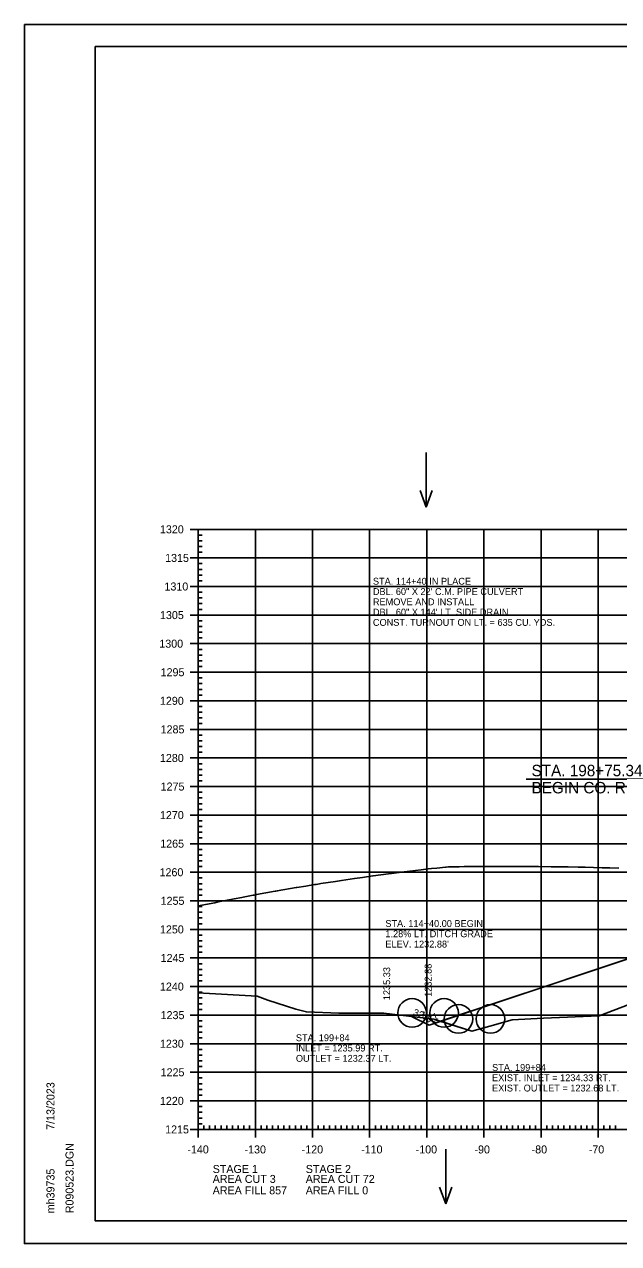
# Model space of a CAD drawing. Extents: x 1406028 to 1412453, y 321733 to 325986.
# Drawn here: x 1406419.5 to 1406523.5, y 323852.7 to 324066 of the extents above; entities that cross this region are included whole.
import ezdxf

# ---------------------------------------------------------------- set-up
doc = ezdxf.new("R2010")
doc.units = 0
for name, color, linetype in [('Default', 7, 'Continuous'), ('R_Axis', 7, 'Continuous'), ('R_Axis Annot', 7, 'Continuous'), ('R_Border', 7, 'Continuous'), ('R_Draft', 7, 'Continuous'), ('R_Drive', 7, 'Continuous'), ('R_Exist Surface', 7, 'Continuous'), ('R_Fin Surface', 7, 'Continuous'), ('R_Fin Surface Annot', 7, 'Continuous'), ('R_Grid', 7, 'Continuous'), ('R_Horz Alg Annot', 7, 'Continuous'), ('R_No Plot', 7, 'Continuous'), ('R_Water', 7, 'Continuous'), ('R_Water Annot', 7, 'Continuous')]:
    doc.layers.add(name, color=color, linetype=linetype)

msp = doc.modelspace()

# ---------------------------------------------------------------- linework, layer by layer
at = {"layer": 'R_Axis'}
for p, q in [((1406448.49, 323977.69), (1406451.29, 323977.69)), ((1406449.89, 323872.69), (1406449.89, 323977.69)), ((1406449.89, 323976.69), (1406450.59, 323976.69)), ((1406449.89, 323975.69), (1406450.59, 323975.69)), ((1406449.89, 323974.69), (1406450.59, 323974.69)), ((1406448.49, 323972.69), (1406451.29, 323972.69)), ((1406449.89, 323973.69), (1406450.59, 323973.69)), ((1406449.89, 323971.69), (1406450.59, 323971.69)), ((1406449.89, 323970.69), (1406450.59, 323970.69)), ((1406449.89, 323969.69), (1406450.59, 323969.69)), ((1406449.89, 323968.69), (1406450.59, 323968.69)), ((1406448.49, 323967.69), (1406451.29, 323967.69)), ((1406449.89, 323966.69), (1406450.59, 323966.69)), ((1406449.89, 323965.69), (1406450.59, 323965.69)), ((1406449.89, 323964.69), (1406450.59, 323964.69)), ((1406448.49, 323962.69), (1406451.29, 323962.69)), ((1406449.89, 323963.69), (1406450.59, 323963.69)), ((1406449.89, 323961.69), (1406450.59, 323961.69)), ((1406449.89, 323960.69), (1406450.59, 323960.69)), ((1406449.89, 323959.69), (1406450.59, 323959.69)), ((1406448.49, 323957.69), (1406451.29, 323957.69)), ((1406449.89, 323958.69), (1406450.59, 323958.69)), ((1406449.89, 323956.69), (1406450.59, 323956.69)), ((1406449.89, 323955.69), (1406450.59, 323955.69)), ((1406449.89, 323954.69), (1406450.59, 323954.69)), ((1406449.89, 323953.69), (1406450.59, 323953.69)), ((1406448.49, 323952.69), (1406451.29, 323952.69)), ((1406449.89, 323951.69), (1406450.59, 323951.69)), ((1406449.89, 323950.69), (1406450.59, 323950.69)), ((1406449.89, 323949.69), (1406450.59, 323949.69)), ((1406448.49, 323947.69), (1406451.29, 323947.69)), ((1406449.89, 323948.69), (1406450.59, 323948.69)), ((1406449.89, 323946.69), (1406450.59, 323946.69)), ((1406449.89, 323945.69), (1406450.59, 323945.69)), ((1406449.89, 323944.69), (1406450.59, 323944.69)), ((1406448.49, 323942.69), (1406451.29, 323942.69)), ((1406449.89, 323943.69), (1406450.59, 323943.69)), ((1406449.89, 323941.69), (1406450.59, 323941.69)), ((1406449.89, 323940.69), (1406450.59, 323940.69)), ((1406449.89, 323939.69), (1406450.59, 323939.69)), ((1406449.89, 323938.69), (1406450.59, 323938.69)), ((1406448.49, 323937.69), (1406451.29, 323937.69)), ((1406449.89, 323936.69), (1406450.59, 323936.69)), ((1406449.89, 323935.69), (1406450.59, 323935.69)), ((1406449.89, 323934.69), (1406450.59, 323934.69)), ((1406448.49, 323932.69), (1406451.29, 323932.69)), ((1406449.89, 323933.69), (1406450.59, 323933.69)), ((1406449.89, 323931.69), (1406450.59, 323931.69)), ((1406449.89, 323930.69), (1406450.59, 323930.69)), ((1406449.89, 323929.69), (1406450.59, 323929.69)), ((1406448.49, 323927.69), (1406451.29, 323927.69)), ((1406449.89, 323928.69), (1406450.59, 323928.69)), ((1406449.89, 323926.69), (1406450.59, 323926.69)), ((1406449.89, 323925.69), (1406450.59, 323925.69)), ((1406449.89, 323924.69), (1406450.59, 323924.69)), ((1406449.89, 323923.69), (1406450.59, 323923.69)), ((1406448.49, 323922.69), (1406451.29, 323922.69)), ((1406449.89, 323921.69), (1406450.59, 323921.69)), ((1406449.89, 323920.69), (1406450.59, 323920.69)), ((1406449.89, 323919.69), (1406450.59, 323919.69)), ((1406448.49, 323917.69), (1406451.29, 323917.69)), ((1406449.89, 323918.69), (1406450.59, 323918.69)), ((1406449.89, 323916.69), (1406450.59, 323916.69)), ((1406449.89, 323915.69), (1406450.59, 323915.69)), ((1406448.49, 323912.69), (1406451.29, 323912.69)), ((1406449.89, 323914.69), (1406450.59, 323914.69)), ((1406449.89, 323913.69), (1406450.59, 323913.69)), ((1406449.89, 323911.69), (1406450.59, 323911.69)), ((1406449.89, 323910.69), (1406450.59, 323910.69)), ((1406449.89, 323909.69), (1406450.59, 323909.69)), ((1406449.89, 323908.69), (1406450.59, 323908.69)), ((1406448.49, 323907.69), (1406451.29, 323907.69)), ((1406449.89, 323906.69), (1406450.59, 323906.69)), ((1406449.89, 323905.69), (1406450.59, 323905.69)), ((1406449.89, 323904.69), (1406450.59, 323904.69)), ((1406448.49, 323902.69), (1406451.29, 323902.69)), ((1406449.89, 323903.69), (1406450.59, 323903.69)), ((1406449.89, 323901.69), (1406450.59, 323901.69)), ((1406449.89, 323900.69), (1406450.59, 323900.69)), ((1406448.49, 323897.69), (1406451.29, 323897.69)), ((1406449.89, 323899.69), (1406450.59, 323899.69)), ((1406449.89, 323898.69), (1406450.59, 323898.69)), ((1406449.89, 323896.69), (1406450.59, 323896.69)), ((1406449.89, 323895.69), (1406450.59, 323895.69)), ((1406449.89, 323894.69), (1406450.59, 323894.69)), ((1406449.89, 323893.69), (1406450.59, 323893.69)), ((1406448.49, 323892.69), (1406451.29, 323892.69)), ((1406449.89, 323891.69), (1406450.59, 323891.69)), ((1406449.89, 323890.69), (1406450.59, 323890.69)), ((1406449.89, 323889.69), (1406450.59, 323889.69)), ((1406448.49, 323887.69), (1406451.29, 323887.69)), ((1406449.89, 323888.69), (1406450.59, 323888.69)), ((1406449.89, 323886.69), (1406450.59, 323886.69)), ((1406449.89, 323885.69), (1406450.59, 323885.69)), ((1406449.89, 323884.69), (1406450.59, 323884.69)), ((1406449.89, 323883.69), (1406450.59, 323883.69)), ((1406448.49, 323882.69), (1406451.29, 323882.69)), ((1406449.89, 323881.69), (1406450.59, 323881.69)), ((1406449.89, 323880.69), (1406450.59, 323880.69)), ((1406449.89, 323879.69), (1406450.59, 323879.69)), ((1406449.89, 323878.69), (1406450.59, 323878.69)), ((1406448.49, 323877.69), (1406451.29, 323877.69)), ((1406449.89, 323876.69), (1406450.59, 323876.69)), ((1406449.89, 323875.69), (1406450.59, 323875.69)), ((1406449.89, 323874.69), (1406450.59, 323874.69)), ((1406448.49, 323872.69), (1406451.29, 323872.69)), ((1406449.89, 323871.29), (1406449.89, 323874.09)), ((1406449.89, 323873.69), (1406450.59, 323873.69)), ((1406449.89, 323872.69), (1406729.89, 323872.69)), ((1406450.89, 323872.69), (1406450.89, 323873.39)), ((1406451.89, 323872.69), (1406451.89, 323873.39)), ((1406452.89, 323872.69), (1406452.89, 323873.39)), ((1406453.89, 323872.69), (1406453.89, 323873.39)), ((1406454.89, 323872.69), (1406454.89, 323873.39)), ((1406455.89, 323872.69), (1406455.89, 323873.39)), ((1406456.89, 323872.69), (1406456.89, 323873.39)), ((1406457.89, 323872.69), (1406457.89, 323873.39)), ((1406458.89, 323872.69), (1406458.89, 323873.39)), ((1406459.89, 323871.29), (1406459.89, 323874.09)), ((1406460.89, 323872.69), (1406460.89, 323873.39)), ((1406461.89, 323872.69), (1406461.89, 323873.39)), ((1406462.89, 323872.69), (1406462.89, 323873.39)), ((1406463.89, 323872.69), (1406463.89, 323873.39)), ((1406464.89, 323872.69), (1406464.89, 323873.39)), ((1406465.89, 323872.69), (1406465.89, 323873.39)), ((1406466.89, 323872.69), (1406466.89, 323873.39)), ((1406467.89, 323872.69), (1406467.89, 323873.39)), ((1406468.89, 323872.69), (1406468.89, 323873.39)), ((1406469.89, 323871.29), (1406469.89, 323874.09)), ((1406470.89, 323872.69), (1406470.89, 323873.39)), ((1406471.89, 323872.69), (1406471.89, 323873.39)), ((1406472.89, 323872.69), (1406472.89, 323873.39)), ((1406473.89, 323872.69), (1406473.89, 323873.39)), ((1406474.89, 323872.69), (1406474.89, 323873.39)), ((1406475.89, 323872.69), (1406475.89, 323873.39)), ((1406476.89, 323872.69), (1406476.89, 323873.39)), ((1406477.89, 323872.69), (1406477.89, 323873.39)), ((1406478.89, 323872.69), (1406478.89, 323873.39)), ((1406479.89, 323871.29), (1406479.89, 323874.09)), ((1406480.89, 323872.69), (1406480.89, 323873.39)), ((1406481.89, 323872.69), (1406481.89, 323873.39)), ((1406482.89, 323872.69), (1406482.89, 323873.39)), ((1406483.89, 323872.69), (1406483.89, 323873.39)), ((1406484.89, 323872.69), (1406484.89, 323873.39)), ((1406485.89, 323872.69), (1406485.89, 323873.39)), ((1406486.89, 323872.69), (1406486.89, 323873.39)), ((1406487.89, 323872.69), (1406487.89, 323873.39)), ((1406488.89, 323872.69), (1406488.89, 323873.39)), ((1406489.89, 323871.29), (1406489.89, 323874.09)), ((1406490.89, 323872.69), (1406490.89, 323873.39)), ((1406491.89, 323872.69), (1406491.89, 323873.39)), ((1406492.89, 323872.69), (1406492.89, 323873.39)), ((1406493.89, 323872.69), (1406493.89, 323873.39)), ((1406494.89, 323872.69), (1406494.89, 323873.39)), ((1406495.89, 323872.69), (1406495.89, 323873.39)), ((1406496.89, 323872.69), (1406496.89, 323873.39)), ((1406497.89, 323872.69), (1406497.89, 323873.39)), ((1406498.89, 323872.69), (1406498.89, 323873.39)), ((1406499.89, 323871.29), (1406499.89, 323874.09)), ((1406500.89, 323872.69), (1406500.89, 323873.39)), ((1406501.89, 323872.69), (1406501.89, 323873.39)), ((1406502.89, 323872.69), (1406502.89, 323873.39)), ((1406503.89, 323872.69), (1406503.89, 323873.39)), ((1406504.89, 323872.69), (1406504.89, 323873.39)), ((1406505.89, 323872.69), (1406505.89, 323873.39)), ((1406506.89, 323872.69), (1406506.89, 323873.39)), ((1406507.89, 323872.69), (1406507.89, 323873.39)), ((1406508.89, 323872.69), (1406508.89, 323873.39)), ((1406509.89, 323871.29), (1406509.89, 323874.09)), ((1406510.89, 323872.69), (1406510.89, 323873.39)), ((1406511.89, 323872.69), (1406511.89, 323873.39)), ((1406512.89, 323872.69), (1406512.89, 323873.39)), ((1406513.89, 323872.69), (1406513.89, 323873.39)), ((1406514.89, 323872.69), (1406514.89, 323873.39)), ((1406515.89, 323872.69), (1406515.89, 323873.39)), ((1406516.89, 323872.69), (1406516.89, 323873.39)), ((1406517.89, 323872.69), (1406517.89, 323873.39)), ((1406518.89, 323872.69), (1406518.89, 323873.39)), ((1406519.89, 323871.29), (1406519.89, 323874.09)), ((1406520.89, 323872.69), (1406520.89, 323873.39)), ((1406521.89, 323872.69), (1406521.89, 323873.39)), ((1406522.89, 323872.69), (1406522.89, 323873.39))]:
    msp.add_line(p, q, dxfattribs=at)
at = {"layer": 'R_Axis Annot'}
msp.add_line((1406507.3, 323933.99), (1406537.31, 323933.99), dxfattribs=at)
at = {"layer": 'R_Border'}
for p, q in [((1406431.89, 324062.15), (1406748.07, 324062.15)), ((1406431.89, 323856.69), (1406431.89, 324062.15)), ((1406431.89, 323856.69), (1406431.89, 323856.69)), ((1406748.07, 323856.69), (1406431.89, 323856.69))]:
    msp.add_line(p, q, dxfattribs=at)
at = {"layer": 'R_Exist Surface'}
msp.add_lwpolyline([(1406449.89, 323896.58), (1406450.83, 323896.53), (1406460.23, 323896.02), (1406462.1, 323895.33), (1406466.95, 323893.73), (1406468.82, 323893.25), (1406474.52, 323893.03), (1406482.35, 323893.02), (1406491.1, 323891.96), (1406491.18, 323891.96), (1406491.23, 323891.94), (1406497.79, 323889.9), (1406500.93, 323890.78), (1406504.83, 323891.87), (1406510.29, 323892.16), (1406520.03, 323892.56), (1406532.75, 323897.43)], dxfattribs=at)
at = {"layer": 'R_Fin Surface'}
for points in [[(1406449.89, 323911.79), (1406452.79, 323912.36), (1406453.2, 323912.45), (1406453.99, 323912.61), (1406454.03, 323912.62), (1406455.89, 323912.97), (1406456.17, 323913.03), (1406457.5, 323913.29), (1406457.78, 323913.35), (1406459.53, 323913.67), (1406459.68, 323913.71), (1406459.95, 323913.76), (1406460.08, 323913.78), (1406463.37, 323914.37), (1406463.48, 323914.39), (1406463.72, 323914.43), (1406467.05, 323915), (1406467.16, 323915.02), (1406468.75, 323915.28), (1406470.25, 323915.53), (1406470.55, 323915.57), (1406471.11, 323915.66), (1406471.14, 323915.67), (1406471.35, 323915.7), (1406473.9, 323916.1), (1406474.94, 323916.25), (1406477.22, 323916.59), (1406478.66, 323916.79), (1406480.43, 323917.04), (1406480.47, 323917.05), (1406480.49, 323917.05), (1406483.21, 323917.41), (1406483.74, 323917.48), (1406485.94, 323917.76), (1406486.95, 323917.88), (1406488.89, 323918.11), (1406490.13, 323918.26), (1406490.7, 323918.32), (1406491.65, 323918.43), (1406493.18, 323918.59), (1406493.28, 323918.6), (1406493.67, 323918.64), (1406495.56, 323918.66), (1406496.4, 323918.67), (1406497.73, 323918.68), (1406499.5, 323918.69), (1406499.9, 323918.69), (1406500.9, 323918.7), (1406502.53, 323918.7), (1406502.53, 323918.7), (1406502.57, 323918.7), (1406502.75, 323918.7), (1406505.62, 323918.7), (1406508.01, 323918.68), (1406508.65, 323918.68), (1406509.41, 323918.67), (1406511.66, 323918.65), (1406512.64, 323918.64), (1406513.13, 323918.63), (1406513.68, 323918.62), (1406514.65, 323918.61), (1406516.36, 323918.58), (1406517.62, 323918.56), (1406519.07, 323918.52), (1406520.58, 323918.49), (1406521.9, 323918.46), (1406523.51, 323918.41)], [(1406487.35, 323892.42), (1406490.29, 323890.94), (1406491.33, 323891.28), (1406491.35, 323891.29), (1406491.5, 323891.34), (1406536.78, 323906.43)]]:
    msp.add_lwpolyline(points, dxfattribs=at)
at = {"layer": 'R_Grid'}
for p, q in [((1406449.89, 323977.69), (1406729.89, 323977.69)), ((1406449.89, 323872.69), (1406449.89, 323977.69)), ((1406459.89, 323872.69), (1406459.89, 323977.69)), ((1406469.89, 323872.69), (1406469.89, 323977.69)), ((1406479.89, 323872.69), (1406479.89, 323977.69)), ((1406489.89, 323872.69), (1406489.89, 323977.69)), ((1406499.89, 323872.69), (1406499.89, 323977.69)), ((1406509.89, 323872.69), (1406509.89, 323977.69)), ((1406519.89, 323872.69), (1406519.89, 323977.69)), ((1406449.89, 323972.69), (1406729.89, 323972.69)), ((1406449.89, 323967.69), (1406729.89, 323967.69)), ((1406449.89, 323962.69), (1406729.89, 323962.69)), ((1406449.89, 323957.69), (1406729.89, 323957.69)), ((1406449.89, 323952.69), (1406729.89, 323952.69)), ((1406449.89, 323947.69), (1406729.89, 323947.69)), ((1406449.89, 323942.69), (1406729.89, 323942.69)), ((1406449.89, 323937.69), (1406729.89, 323937.69)), ((1406449.89, 323932.69), (1406729.89, 323932.69)), ((1406449.89, 323927.69), (1406729.89, 323927.69)), ((1406449.89, 323922.69), (1406729.89, 323922.69)), ((1406449.89, 323917.69), (1406729.89, 323917.69)), ((1406449.89, 323912.69), (1406729.89, 323912.69)), ((1406449.89, 323907.69), (1406729.89, 323907.69)), ((1406449.89, 323902.69), (1406729.89, 323902.69)), ((1406449.89, 323897.69), (1406729.89, 323897.69)), ((1406449.89, 323892.69), (1406729.89, 323892.69)), ((1406449.89, 323887.69), (1406729.89, 323887.69)), ((1406449.89, 323882.69), (1406729.89, 323882.69)), ((1406449.89, 323877.69), (1406729.89, 323877.69)), ((1406449.89, 323872.69), (1406729.89, 323872.69))]:
    msp.add_line(p, q, dxfattribs=at)
at = {"layer": 'R_No Plot'}
for p, q in [((1406419.49, 324066.05), (1406752.82, 324066.05)), ((1406419.49, 323852.71), (1406752.82, 323852.71))]:
    msp.add_line(p, q, dxfattribs=at)
for points in [[(1406419.48, 324066.05), (1406752.82, 324066.05), (1406752.82, 323852.71), (1406419.48, 323852.71)], [(1406665.81, 324062.15), (1406685.43, 324062.15), (1406685.43, 324052.27), (1406701.54, 324052.27), (1406724.74, 324052.27), (1406724.74, 324027.94), (1406748.07, 324027.94), (1406748.07, 323856.69), (1406431.89, 323856.69), (1406431.89, 324062.15)], [(1406490.45, 323891.85), (1406490.45, 323892.04), (1406491.1, 323891.96), (1406491.18, 323891.96), (1406491.23, 323891.94), (1406492.31, 323891.61), (1406491.63, 323891.38), (1406491.48, 323891.33)]]:
    msp.add_lwpolyline(points, close=True, dxfattribs=at)
msp.add_lwpolyline([(1406557.86, 323913.46), (1406512.15, 323898.21), (1406492.31, 323891.61), (1406497.79, 323889.9), (1406500.93, 323890.78), (1406504.83, 323891.87), (1406510.29, 323892.16), (1406520.03, 323892.56), (1406532.75, 323897.43)], dxfattribs=at)
at = {"layer": 'R_Water'}
for centre in [(1406487.32, 323893.08), (1406492.92, 323893.08), (1406495.43, 323892.03), (1406501.03, 323892.03)]:
    msp.add_circle(centre, 2.5, dxfattribs=at)
at = {"layer": 'R_Water Annot'}
for p, q in [((1406489.79, 323991.14), (1406489.79, 323981.56)), ((1406489.79, 323981.56), (1406488.72, 323984.49)), ((1406489.79, 323981.56), (1406490.85, 323984.49)), ((1406493.2, 323869.23), (1406493.2, 323859.66)), ((1406493.2, 323859.66), (1406492.13, 323862.59)), ((1406493.2, 323859.66), (1406494.27, 323862.59))]:
    msp.add_line(p, q, dxfattribs=at)

# ---------------------------------------------------------------- texts
at = {"layer": 'Default'}
for s, p in [('STA. 114+40 IN PLACE', (1406480.46, 323968.01)), ('DBL. 60" X 22\' C.M. PIPE CULVERT', (1406480.46, 323966.21)), ('REMOVE AND INSTALL', (1406480.46, 323964.41)), ('DBL. 60" X 144\' LT. SIDE DRAIN', (1406480.46, 323962.61)), ('CONST. TURNOUT ON LT. = 635 CU. YDS. ', (1406480.46, 323960.81))]:
    msp.add_text(s, height=1.2, rotation=360, dxfattribs=at).set_placement(p)
at = {"layer": 'R_Axis Annot'}
for s, p in [('1320', (1406443.2, 323976.99)), ('1315', (1406444.11, 323971.99)), ('1310', (1406443.99, 323966.99)), ('1305', (1406443.21, 323961.99)), ('1300', (1406443.09, 323956.99)), ('1295', (1406443.32, 323951.99)), ('1290', (1406443.2, 323946.99)), ('1285', (1406443.32, 323941.99)), ('1280', (1406443.2, 323936.99)), ('1275', (1406443.32, 323931.99)), ('1270', (1406443.2, 323926.99)), ('1265', (1406443.25, 323921.99)), ('1260', (1406443.13, 323916.99)), ('1255', (1406443.32, 323911.99)), ('1250', (1406443.2, 323906.99)), ('1245', (1406443.32, 323901.99)), ('1240', (1406443.2, 323896.99)), ('1235', (1406443.32, 323891.99)), ('1230', (1406443.2, 323886.99)), ('1225', (1406443.32, 323881.99)), ('1220', (1406443.2, 323876.99)), ('1215', (1406444.11, 323871.99)), ('-140', (1406448, 323868.49)), ('-130', (1406458, 323868.49)), ('-120', (1406468, 323868.49)), ('-110', (1406478.4, 323868.49)), ('-100', (1406487.94, 323868.49)), ('-90', (1406498.23, 323868.49)), ('-80', (1406508.23, 323868.49)), ('-70', (1406518.23, 323868.49)), ('STAGE 1', (1406452.43, 323865.07)), ('STAGE 2', (1406468.71, 323865.07)), ('AREA CUT 3', (1406452.43, 323863.33)), ('AREA CUT 72', (1406468.71, 323863.33)), ('AREA FILL 857', (1406452.43, 323861.33)), ('AREA FILL 0', (1406468.71, 323861.33))]:
    msp.add_text(s, height=1.4, dxfattribs=at).set_placement(p)
at = {"layer": 'R_Border'}
for s, p in [('7/13/2023', (1406424.75, 323872.62)), ('R090523.DGN', (1406428.08, 323858.02)), ('mh39735', (1406424.75, 323858.02))]:
    msp.add_text(s, height=1.4, rotation=90, dxfattribs=at).set_placement(p)
at = {"layer": 'R_Draft'}
for s, p in [('STA. 198+75.34', (1406508.22, 323934.49)), ('BEGIN CO. RD. 8530', (1406508.22, 323931.49))]:
    msp.add_text(s, height=2, dxfattribs=at).set_placement(p)
at = {"layer": 'R_Drive'}
for s, p in [('STA. 114+40.00 BEGIN', (1406482.64, 323908.12)), ('1.28% LT. DITCH GRADE', (1406482.64, 323906.32)), ("ELEV. 1232.88'", (1406482.64, 323904.52))]:
    msp.add_text(s, height=1.2, dxfattribs=at).set_placement(p)
at = {"layer": 'R_Fin Surface Annot'}
for s, rotation, p in [('1235.33', 90, (1406483.48, 323895.3)), ('1232.88', 90, (1406490.73, 323895.89)), ('3:1', 341.5668, (1406487.41, 323892.7)), ('2:1', 333.3809, (1406488.3, 323892.5)), ('3:1', 18.189, (1406489.86, 323891.33))]:
    msp.add_text(s, height=1.2, rotation=rotation, dxfattribs=at).set_placement(p)
at = {"layer": 'R_Horz Alg Annot'}
for s, p in [('STA. 199+84', (1406466.98, 323888.13)), ('INLET = 1235.99 RT.', (1406466.98, 323886.33)), ('OUTLET = 1232.37 LT.', (1406466.98, 323884.53)), ('STA. 199+84', (1406501.31, 323882.93)), ('EXIST. INLET = 1234.33 RT.', (1406501.31, 323881.13)), ('EXIST. OUTLET = 1232.68 LT.', (1406501.31, 323879.33))]:
    msp.add_text(s, height=1.2, dxfattribs=at).set_placement(p)
at = {"layer": 'R_No Plot'}
for p in [(1406460.19, 323895.97), (1406468.78, 323893.2), (1406482.3, 323892.97), (1406491.14, 323891.91), (1406504.79, 323891.82), (1406519.99, 323892.51), (1406497.75, 323889.85)]:
    msp.add_text('+', height=0.1, dxfattribs=at).set_placement(p)

doc.saveas('drawing.dxf')
